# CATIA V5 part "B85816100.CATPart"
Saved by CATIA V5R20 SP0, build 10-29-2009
Part number: B85816100
Revision: 3
Definition: design
Nomenclature: B85816100
Source: made
Description: NOT SPECIFIED
Bounding box of the stored display mesh (mm): x -10 to 10, y -10 to 10, z 0 to 100
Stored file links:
  C:\Users\Raffaele\Desktop\3D X SITO CF\BOLEX\12-PILLAR REF 858\B85816100.CATPart
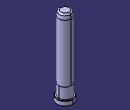
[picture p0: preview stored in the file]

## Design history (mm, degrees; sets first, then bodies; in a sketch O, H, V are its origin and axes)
Body1 "MANIFOLD_SOLID_BREP #450" (main body)
  Solid1: solid without history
